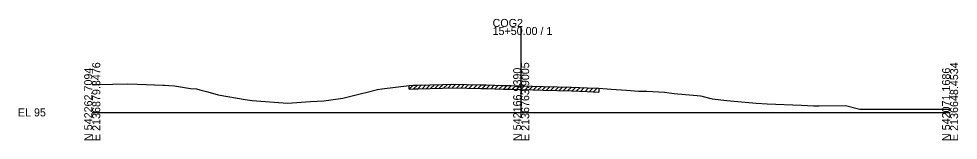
# Model space of a CAD drawing. Extents: x -13397 to 2303, y -10 to 39059.
# Drawn here: x -25.7 to 302.8, y 10990.3 to 11032.6 of the extents above; entities that cross this region are included whole.
import ezdxf

# ---------------------------------------------------------------- set-up
doc = ezdxf.new("R2010")
doc.units = 0
for name, color, linetype in [('RD_GPK_XS_Cell', 7, 'Continuous'), ('RD_XS_ExGround', 7, 'Continuous'), ('RD_XS_ExPaveRet', 7, 'Continuous'), ('RD_XS_TX_Elev_EX', 7, 'Continuous')]:
    doc.layers.add(name, color=color, linetype=linetype)

msp = doc.modelspace()

# ---------------------------------------------------------------- linework, layer by layer
at = {"layer": 'RD_GPK_XS_Cell'}
for p, q in [((150, 11000), (150, 11029.81)), ((0, 11000), (150, 11000)), ((150, 11000), (300, 11000))]:
    msp.add_line(p, q, dxfattribs=at)
at = {"layer": 'RD_XS_ExGround'}
for p, q in [((0, 11009.72), (0.17, 11009.72)), ((0.17, 11009.72), (1.84, 11009.75)), ((1.84, 11009.75), (12.37, 11009.94)), ((12.37, 11009.94), (15.85, 11009.83)), ((15.85, 11009.83), (24.78, 11009.55)), ((24.78, 11009.55), (25.29, 11009.52)), ((25.29, 11009.52), (26.82, 11009.43)), ((26.82, 11009.43), (28.78, 11009.22)), ((28.78, 11009.22), (34.36, 11008.38)), ((101.3, 11008.21), (110.84, 11009.43)), ((110.84, 11009.43), (112.29, 11009.48)), ((112.29, 11009.48), (113.84, 11009.53)), ((113.84, 11009.53), (122.45, 11009.74)), ((122.45, 11009.74), (126.24, 11009.83)), ((126.24, 11009.83), (135.84, 11009.63)), ((135.84, 11009.63), (137.76, 11009.59)), ((137.76, 11009.59), (143.83, 11009.44)), ((143.83, 11009.44), (146.33, 11009.38)), ((146.33, 11009.38), (150, 11009.24)), ((150, 11009.24), (150.33, 11009.23)), ((150.33, 11009.23), (157.66, 11009.08)), ((34.36, 11008.38), (36.46, 11008.17)), ((36.46, 11008.17), (37.62, 11007.92)), ((37.62, 11007.92), (40.37, 11007.16)), ((40.37, 11007.16), (44.06, 11006.14)), ((44.06, 11006.14), (53.43, 11004.53)), ((87.67, 11004.94), (94.65, 11006.71)), ((94.65, 11006.71), (95.71, 11006.99)), ((95.71, 11006.99), (99.7, 11008.01)), ((99.7, 11008.01), (101.3, 11008.21)), ((157.66, 11009.08), (167.63, 11008.86)), ((167.63, 11008.86), (173.05, 11008.58)), ((173.05, 11008.58), (177.15, 11008.41)), ((177.15, 11008.41), (181.52, 11008.1)), ((181.52, 11008.1), (186.79, 11007.76)), ((186.79, 11007.76), (191.08, 11007.46)), ((191.08, 11007.46), (193.96, 11007.4)), ((193.96, 11007.4), (200.09, 11007.07)), ((200.09, 11007.07), (203.48, 11006.58)), ((203.48, 11006.58), (210.17, 11006.01)), ((210.17, 11006.01), (211.5, 11005.87)), ((211.5, 11005.87), (212.7, 11005.73)), ((53.43, 11004.53), (55.93, 11004.14)), ((55.93, 11004.14), (57.4, 11003.99)), ((57.4, 11003.99), (68.33, 11003.26)), ((68.33, 11003.26), (76.31, 11003.76)), ((76.31, 11003.76), (81.04, 11004.05)), ((81.04, 11004.05), (83.39, 11004.36)), ((83.39, 11004.36), (87.67, 11004.94)), ((212.7, 11005.73), (213.27, 11005.69)), ((213.27, 11005.69), (213.64, 11005.58)), ((213.64, 11005.58), (216.81, 11004.69)), ((216.81, 11004.69), (221.9, 11004.15)), ((221.9, 11004.15), (232.18, 11003.26)), ((232.18, 11003.26), (236.04, 11002.93)), ((236.04, 11002.93), (248.03, 11002.48)), ((248.03, 11002.48), (252.18, 11002.34)), ((252.18, 11002.34), (254.23, 11002.27)), ((254.23, 11002.27), (263.37, 11002.38)), ((263.37, 11002.38), (267.98, 11001.24)), ((267.98, 11001.24), (268.41, 11001.13)), ((268.41, 11001.13), (268.8, 11001.13)), ((268.8, 11001.13), (273.77, 11001.13)), ((273.77, 11001.13), (285.31, 11001.13)), ((285.31, 11001.13), (286.25, 11001.13)), ((286.25, 11001.13), (289.56, 11001.13)), ((289.56, 11001.13), (294.53, 11001.13)), ((294.53, 11001.13), (300, 11001.13))]:
    msp.add_line(p, q, dxfattribs=at)
at = {"layer": 'RD_XS_ExPaveRet'}
for p, q in [((110.84, 11008.13), (112.19, 11009.48)), ((110.84, 11008.13), (110.84, 11009.43)), ((112.34, 11008.19), (113.69, 11009.53)), ((113.84, 11008.23), (115.18, 11009.57)), ((115.34, 11008.27), (116.68, 11009.6)), ((116.84, 11008.31), (118.18, 11009.64)), ((118.34, 11008.34), (119.68, 11009.67)), ((119.84, 11008.38), (121.18, 11009.71)), ((121.34, 11008.41), (122.68, 11009.75)), ((122.84, 11008.45), (124.18, 11009.78)), ((124.34, 11008.49), (125.68, 11009.82)), ((125.84, 11008.52), (127.13, 11009.82)), ((127.34, 11008.51), (128.62, 11009.78)), ((128.84, 11008.48), (130.12, 11009.75)), ((130.34, 11008.45), (131.62, 11009.72)), ((131.84, 11008.42), (133.12, 11009.69)), ((133.34, 11008.38), (134.62, 11009.66)), ((134.84, 11008.35), (136.12, 11009.63)), ((136.34, 11008.32), (137.62, 11009.59)), ((137.84, 11008.29), (139.11, 11009.56)), ((139.34, 11008.25), (140.61, 11009.52)), ((140.84, 11008.21), (142.11, 11009.48)), ((142.34, 11008.18), (143.61, 11009.44)), ((143.84, 11008.14), (145.11, 11009.41)), ((145.34, 11008.1), (146.61, 11009.37)), ((146.84, 11008.06), (148.1, 11009.31)), ((148.34, 11008), (149.6, 11009.26)), ((149.84, 11007.95), (151.11, 11009.21)), ((151.34, 11007.91), (152.62, 11009.18)), ((152.84, 11007.88), (154.12, 11009.15)), ((110.84, 11008.13), (112.29, 11008.18)), ((112.29, 11008.18), (113.84, 11008.23)), ((113.84, 11008.23), (122.45, 11008.44)), ((122.45, 11008.44), (126.24, 11008.53)), ((126.24, 11008.53), (135.84, 11008.33)), ((135.84, 11008.33), (137.76, 11008.29)), ((137.76, 11008.29), (143.83, 11008.14)), ((143.83, 11008.14), (146.33, 11008.08)), ((146.33, 11008.08), (150, 11007.94)), ((150, 11007.94), (150.33, 11007.93)), ((150.33, 11007.93), (157.66, 11007.78)), ((154.34, 11007.85), (155.62, 11009.12)), ((155.84, 11007.82), (157.12, 11009.09)), ((157.34, 11007.79), (158.62, 11009.06)), ((157.66, 11007.78), (167.63, 11007.56)), ((158.84, 11007.75), (160.12, 11009.02)), ((160.34, 11007.72), (161.62, 11008.99)), ((161.84, 11007.69), (163.12, 11008.96)), ((163.34, 11007.65), (164.62, 11008.92)), ((164.84, 11007.62), (166.12, 11008.89)), ((166.34, 11007.59), (167.62, 11008.86)), ((167.63, 11007.56), (173.05, 11007.28)), ((167.84, 11007.55), (169.08, 11008.78)), ((169.34, 11007.47), (170.58, 11008.71)), ((170.84, 11007.39), (172.08, 11008.63)), ((172.34, 11007.32), (173.59, 11008.56)), ((173.05, 11007.28), (177.15, 11007.11)), ((173.84, 11007.25), (175.09, 11008.49)), ((175.34, 11007.18), (176.59, 11008.43)), ((177.15, 11008.41), (177.15, 11007.11))]:
    msp.add_line(p, q, dxfattribs=at)

# ---------------------------------------------------------------- texts
at = {"layer": 'RD_GPK_XS_Cell'}
for s, p in [('COG2', (140, 11029.81)), ('15+50.00 / 1', (140, 11027.01)), ('EL 95', (-26, 10998.6))]:
    msp.add_text(s, height=2.8, dxfattribs=at).set_placement(p)
for s, p in [('E 2136879.3476', (2.8, 10990)), ('E 2136763.9005', (152.8, 10990)), ('E 2136648.4534', (302.8, 10990)), ('N 542262.7094', (0, 10990)), ('N 542166.9390', (150, 10990)), ('N 542071.1686', (300, 10990))]:
    msp.add_text(s, height=2.8, rotation=90, dxfattribs=at).set_placement(p)
at = {"layer": 'RD_XS_TX_Elev_EX'}
msp.add_text('104.24', height=1, rotation=90, dxfattribs=at).set_placement((150.75, 11010.24))

doc.saveas('drawing.dxf')
